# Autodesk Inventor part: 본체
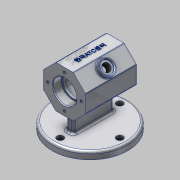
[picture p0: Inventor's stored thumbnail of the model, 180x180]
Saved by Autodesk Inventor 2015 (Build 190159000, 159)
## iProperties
Created: 2021-02
Part Number: 본체
Material: 알루미늄 6061
Document SubType Name: Modeling
Designer: Administrator
Density: 2.7 g/cm^3
Appearance: 알루미늄 - 평지
Mass: 556.749 g
Surface Area: 509.677 cm^2
Volume: 206.203 cm^3
Author: Administrator
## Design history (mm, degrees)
sketch "스케치1"
  geometry: L1 (29, 12.012)-(29, -12.012); L2 (29, -12.012)-(12.012, -29); L3 (12.012, -29)-(-12.012, -29); L4 (-12.012, -29)-(-29, -12.012); L5 (-29, -12.012)-(-29, 12.012); L6 (-29, 12.012)-(-12.012, 29); L7 (-12.012, 29)-(12.012, 29); L8 (12.012, 29)-(29, 12.012)
  constraints: 16 end point
  dimensions: "d0" = 58 distance between parallel lines of L5 L1
extrude "돌출1" new body sketch "스케치1" distance "d3" = 70; taper "d4" = 0 deg
node "작업 평면1"
sketch "스케치2"
  geometry: L1 (0, 0)-(-12, 0); L2 (-12, 0)-(-12, -16); L3 (-12, -16)-(0, -16); L4 (0, -16)-(0, 0); L5 (-12, 0)-(-15, 0); L6 (-15, 0)-(-15, -14); L7 (-15, -14)-(-12, -14); L8 (-12, -14)-(-12, 0); L9 (-15, 0)-(-55, 0); L10 (-55, 0)-(-55, -22); L11 (-55, -22)-(-15, -22); L12 (-15, -22)-(-15, 0); L13 (-55, 0)-(-58, 0); L14 (-58, 0)-(-58, -14); L15 (-58, -14)-(-55, -14); L16 (-55, -14)-(-55, 0); L17 (-58, 0)-(-70, 0); L18 (-70, 0)-(-70, -16); L19 (-70, -16)-(-58, -16); L20 (-58, -16)-(-58, 0)
  constraints: 40 end point, 10 parallel, 5 horizontal, 5 perpendicular
  dimensions: "d6" = 12 distance of L3.end L2.end; "d7" = 16 distance of L2.end L1.end; "d8" = 3 distance of L7.end L6.end; "d9" = 14 distance of L6.end L5.end; "d10" = 40 distance of L11.end L10.end; "d11" = 22 distance of L10.end L9.end; "d12" = 3 distance of L15.end L14.end; "d13" = 14 distance of L14.end L13.end; "d14" = 12 distance of L19.end L18.end; "d15" = 16 distance of L18.end L17.end
revolve "회전1" sketch "스케치2" stored, may be unused: angle "d16" = 90 deg
sketch "스케치3"
  geometry: 1 further point
chamfer "모따기1" distance "d17" = 1; stored, may be unused: second distance "d18" = 2, angle "d19" = 45 deg
fillet "모깎기1" dims "d20" = 0.3
fillet "모깎기2" dims "d21" = 3
node "작업 평면2"
sketch "스케치4"
  geometry: L1 (0, 0)-(0, 24.024) reference; L2 (0, 41.012)-(70, 41.012) reference; C1 r 10 at (35, 12.012); 1 further point
  constraints: 1 centre point
  dimensions: "d23" = 10 radius of C1; "d24" = 35 distance from line of C1.centre L1; "d25" = 29 distance from line of L2 C1.centre
extrude "돌출2" join sketch "스케치4" distance "d26" = 5; taper "d27" = 0 deg
sketch "스케치5"
  geometry: L1 (0, 0)-(0, 24.024) reference; L2 (0, 41.012)-(70, 41.012) reference; C1 r 8 at (35, 12.012); 1 further point
  constraints: 1 centre point
  dimensions: "d28" = 8 radius of C1; "d29" = 35 distance from line of L1 C1.centre; "d30" = 29 distance from line of L2 C1.centre
extrude "돌출3" cut sketch "스케치5" distance "d31" = 2; taper "d32" = 0 deg
sketch "스케치6"
  geometry: C1 r 8 at (0, 0) reference; 2 further points
  constraints: 1 coincident
hole "구멍1" sketch "스케치6" at (0, 0) diameter "d33" = 10.917; stored, may be unused: countersink angle "d37" = 90 deg, drill point angle "d39" = 0 deg; dims "d34" = 24, "d35" = 4, "d36" = 2, "d38" = 29.1
fillet "모깎기3" dims "d40" = 1
chamfer "모따기2" distance "d41" = 1; stored, may be unused: second distance "d42" = 2, angle "d43" = 45 deg
node "작업 평면3"
sketch "스케치7"
  geometry: C1 r 52 at (-35, 0); 1 further point
  constraints: 1 centre point
  dimensions: "d50" = 52 radius of C1
extrude "돌출4" join sketch "스케치7" distance "d51" = 10; taper "d52" = 0 deg
sketch "스케치8"
  geometry: L1 (-28, -5)-(28, -5); L2 (28, -5)-(28, 5); L3 (28, 5)-(-28, 5); L4 (-28, 5)-(-28, -5); C1 r 52 at (0, 0) reference; 1 further point
  constraints: 8 end point, 2 parallel, 1 horizontal, 1 perpendicular
  dimensions: "d53" = 56 distance of L3.end L2.end; "d54" = 10 distance of L2.end L1.end; "d55" = 5 distance from line of L1 C1.centre; "d56" = 28 distance from line of L4 C1.centre
extrude "돌출5" join sketch "스케치8" stored distance "d57" = 10; taper "d58" = 0 deg
sketch "스케치9"
  geometry: C1 r 52 at (0, 0) reference; C2 r 4.5 at (0, 41); C3 r 4.5 at (41, 0); C4 r 4.5 at (0, -41); C5 r 4.5 at (-41, 0); A1 r 41 centre (0, 0) between (0, 41) and (41, 0); 1 further point
  constraints: 5 centre point, 4 point on circle, 1 coincident
  dimensions: "d59" = 41 radius of A1; "d60" = 4.5 radius of C2; "d61" = 4.5 radius of C3; "d62" = 4.5 radius of C4; "d63" = 4.5 radius of C5
extrude "돌출6" cut sketch "스케치9" stored distance "d64" = 10; taper "d65" = 0 deg
sketch "스케치10"
  geometry: C1 r 17 at (0, 0) reference; A1 r 23 centre (0, 0) between (0, 23) and (23, 0); 2 further points
  constraints: 4 point on circle, 1 centre point, 1 coincident
  dimensions: "d66" = 23 radius of A1
hole "구멍2" sketch "스케치10" at (0, 23), (23, 0), (0, -23), (-23, 0) diameter "d67" = 3.242; stored, may be unused: countersink angle "d71" = 90 deg, drill point angle "d73" = 118 deg; dims "d68" = 8, "d69" = 4, "d70" = 2, "d72" = 10
sketch "스케치11"
  geometry: C1 r 17 at (0, 0) reference; A1 r 23 centre (0, 0) between (0, 23) and (23, 0); 2 further points
  constraints: 4 point on circle, 1 centre point, 1 coincident
  dimensions: "d74" = 23 radius of A1
hole "구멍3" sketch "스케치11" at (0, 23), (23, 0), (0, -23), (-23, 0) diameter "d75" = 3.242; stored, may be unused: countersink angle "d79" = 90 deg, drill point angle "d81" = 118 deg; dims "d76" = 8, "d77" = 4, "d78" = 2, "d80" = 10
fillet "모깎기4" dims "d82" = 3
fillet "모깎기5" dims "d83" = 3
fillet "모깎기6" dims "d84" = 3
fillet "모깎기7" dims "d85" = 1
sketch "스케치12"
  geometry: L1 (0, 0)-(0, 23.196) reference; L2 (0, 40.305)-(70, 40.305) reference; 2 further points
  constraints: 1 other
  dimensions: "d86" = 35 distance from line of L1 point (35, 11.305); "d87" = 29 distance from line of L2 point (35, 11.305)
feature "엠보싱1" sketch "스케치12" dims "d0" = 58, "d6" = 12, "d7" = 16, "d8" = 3, "d9" = 14, "d10" = 40, "d11" = 22, "d12" = 3, "d13" = 14, "d14" = 12, "d15" = 16, "d88" = 0.5, "d89" = 0
node "솔리드1"
other parameters: "d5" = 0, "d22" = 5, "d44" = -62
